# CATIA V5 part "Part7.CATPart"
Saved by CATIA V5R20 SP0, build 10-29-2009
Part number: 9FP1808M6
Revision: ANY
Definition: UNKNOWN
Nomenclature: 9FP1808M6
Source: Unknown
Bounding box of the stored display mesh (mm): x -8.9 to 8.9, y 0 to 8, z -8.9 to 8.9
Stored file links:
  C:\Users\Utente\Desktop\IO LAVORO\3D X SITO CF\CUMSA\3D files PW\pw101430\pw101430_injection\Part7.CATPart
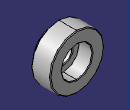
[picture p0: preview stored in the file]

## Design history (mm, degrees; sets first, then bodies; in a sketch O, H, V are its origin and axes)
Body1 "Chaflán1" (main body)
  Solid1: solid without history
